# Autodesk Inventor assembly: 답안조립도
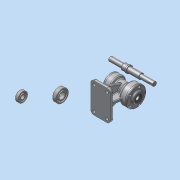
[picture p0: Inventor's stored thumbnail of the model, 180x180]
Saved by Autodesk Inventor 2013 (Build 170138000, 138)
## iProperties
Created: 2015-08
Part Number: 답안조립도
Document SubType Name: Assembly
Designer: Administrator
Author: Administrator
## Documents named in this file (10)
- C:\Users\Administrator\Desktop\450806V1037\답안조립도.iam
- C:\Users\Administrator\Desktop\450806V1037\M4x0.5.ipt
- C:\Users\Administrator\Desktop\450806V1037\뒤커버.ipt
- C:\Users\Administrator\Desktop\450806V1037\베어링 6203.ipt
- C:\Users\Administrator\Desktop\450806V1037\베어링 6205.ipt
- C:\Users\Administrator\Desktop\450806V1037\본체.ipt
- C:\Users\Administrator\Desktop\450806V1037\앞커버.ipt
- C:\Users\Administrator\Desktop\450806V1037\오일실 .ipt
- 오일실 .ipt
- C:\Users\Administrator\Desktop\450806V1037\축.ipt
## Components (6 placed, 1 different names)
1. M4x0.5:1
2. M4x0.5:2
3. M4x0.5:3
4. M4x0.5:4
5. M4x0.5:5
6. M4x0.5:6
